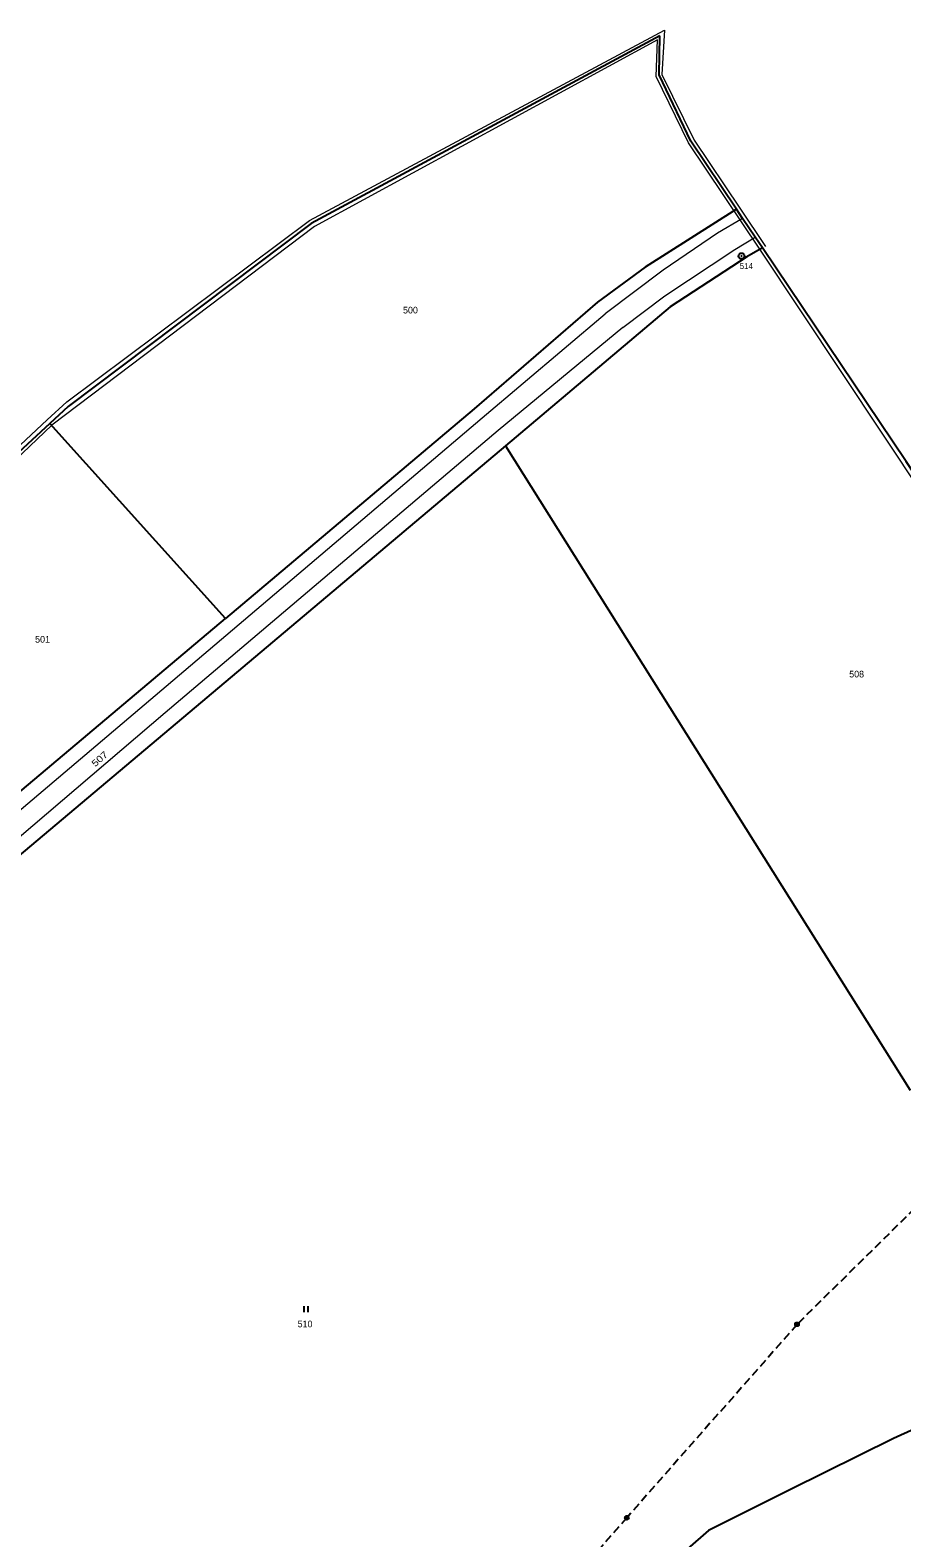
# Model space of a CAD drawing. Extents: x -653193 to -651624, y -1092017 to -1090260.
# Drawn here: x -652283.1 to -652060.5, y -1090861.4 to -1090476.4 of the extents above; entities that cross this region are included whole.
import ezdxf
from ezdxf.enums import TextEntityAlignment as Align

# ---------------------------------------------------------------- set-up
doc = ezdxf.new("R2010")
doc.units = 0
doc.header["$LTSCALE"] = 0.68
doc.linetypes.add('MEDIUM_DASHED', pattern=[4.5, 3, -1.5])
for name, color, linetype, lineweight in [('1', 7, 'Continuous', 25), ('3', 7, 'Continuous', 25), ('4', 7, 'Continuous', 13), ('6', 7, 'Continuous', 25), ('8', 7, 'Continuous', 25)]:
    doc.layers.add(name, color=color, linetype=linetype, lineweight=lineweight)
doc.layers.add('2', color=7, linetype='Continuous')

msp = doc.modelspace()

# ---------------------------------------------------------------- linework, layer by layer
at = {"layer": '1'}
for p, q in [((-652122.25, -1090477.85), (-652211.34, -1090525.8)), ((-652122.44, -1090487.8), (-652122.25, -1090477.85)), ((-652114.39, -1090504.78), (-652122.44, -1090487.8)), ((-652102.72, -1090522.13), (-652114.39, -1090504.78)), ((-652102.72, -1090522.13), (-652126.01, -1090536.93)), ((-652101.13, -1090524.49), (-652102.72, -1090522.13)), ((-652211.34, -1090525.8), (-652273.4, -1090572.52)), ((-652097.89, -1090529.3), (-652101.13, -1090524.49)), ((-652096.08, -1090531.99), (-652097.89, -1090529.3)), ((-652100.06, -1090534.33), (-652119.6, -1090547.06)), ((-652096.08, -1090531.99), (-652100.06, -1090534.33)), ((-652126.01, -1090536.93), (-652138.2, -1090545.89)), ((-652138.2, -1090545.89), (-652169.67, -1090573.11)), ((-652119.6, -1090547.06), (-652161.73, -1090582.58)), ((-652273.4, -1090572.52), (-652278.07, -1090576.84)), ((-652169.67, -1090573.11), (-652233.17, -1090626.65)), ((-652278.07, -1090576.84), (-652308.16, -1090604.7)), ((-652233.17, -1090626.65), (-652278.07, -1090576.84)), ((-652161.73, -1090582.58), (-652237.99, -1090646.81)), ((-652161.73, -1090582.58), (-652058.33, -1090747.05)), ((-652286.71, -1090671.78), (-652233.17, -1090626.65)), ((-652237.99, -1090646.81), (-652287.6, -1090688.58)), ((-652047.04, -1090828.95), (-652062.61, -1090836.05)), ((-652062.61, -1090836.05), (-652088.94, -1090849.09)), ((-652088.94, -1090849.09), (-652109.84, -1090859.51)), ((-652109.84, -1090859.51), (-652115.21, -1090864.22))]:
    msp.add_line(p, q, dxfattribs=at)
msp.add_lwpolyline([(-652012.34, -1090657.94), (-652059.39, -1090586.59), (-652096.08, -1090531.99)], dxfattribs=at)
at = {"layer": '3'}
for p, q in [((-652213.111, -1090803.78), (-652213.111, -1090802.28)), ((-652212.11, -1090803.78), (-652212.11, -1090802.28))]:
    msp.add_line(p, q, dxfattribs=at)
at = {"layer": '4'}
for p, q in [((-652101.13, -1090524.49), (-652107.52, -1090528.27)), ((-652107.52, -1090528.27), (-652121.4, -1090537.73)), ((-652103.13, -1090532.43), (-652097.89, -1090529.3)), ((-652120.97, -1090544.31), (-652103.13, -1090532.43)), ((-652121.4, -1090537.73), (-652136.24, -1090548.9)), ((-652131.72, -1090552.32), (-652120.97, -1090544.31)), ((-652167.64, -1090575.43), (-652136.24, -1090548.9)), ((-652131.72, -1090552.32), (-652163.57, -1090578.68)), ((-652251.17, -1090646.33), (-652167.64, -1090575.43)), ((-652163.57, -1090578.68), (-652248.6, -1090650.75)), ((-652289.3, -1090678.68), (-652251.17, -1090646.33)), ((-652248.6, -1090650.75), (-652289.95, -1090686.08))]:
    msp.add_line(p, q, dxfattribs=at)
for points in [[(-652394.94, -1090666.29), (-652333.98, -1090622.23), (-652308.65, -1090603.85), (-652278.77, -1090575.95), (-652273.68, -1090571.31), (-652211.73, -1090525.03), (-652121.11, -1090476.43), (-652121.78, -1090487.72), (-652113.48, -1090504.55), (-652101.85, -1090521.87), (-652095.29, -1090531.68)], [(-651924.64, -1090810.59), (-651944.72, -1090786.79), (-651953.83, -1090771.34), (-651957.54, -1090759.26), (-651970.54, -1090744.66), (-651971.3, -1090737.57), (-651990.03, -1090683.62), (-652010.36, -1090668.34), (-652012.98, -1090658.29), (-652096.76, -1090532.33), (-652114.98, -1090505.23), (-652123.25, -1090488.26), (-652122.91, -1090478.89), (-652210.49, -1090526.59), (-652277.57, -1090577.33), (-652307.52, -1090605.78), (-652393.41, -1090667.24), (-652434.16, -1090726.25)]]:
    msp.add_lwpolyline(points, dxfattribs=at)
at = {"layer": '6', "linetype": 'MEDIUM_DASHED'}
for p, q in [((-652037.57, -1090757.97), (-652087.24, -1090806.89)), ((-652087.24, -1090806.89), (-652130.7, -1090856.28)), ((-652130.7, -1090856.28), (-652183.19, -1090915.5))]:
    msp.add_line(p, q, dxfattribs=at)
at = {"layer": '6'}
for centre, radius in [((-652087.2434, -1090806.8899), 0.5), ((-652087.2434, -1090806.8899), 0.4), ((-652087.2434, -1090806.8899), 0.3), ((-652087.2434, -1090806.8899), 0.2), ((-652087.2434, -1090806.8899), 0.1), ((-652130.7034, -1090856.2799), 0.5), ((-652130.7034, -1090856.2799), 0.4), ((-652130.7034, -1090856.2799), 0.3), ((-652130.7034, -1090856.2799), 0.2), ((-652130.7034, -1090856.2799), 0.1)]:
    msp.add_circle(centre, radius, dxfattribs=at)
at = {"layer": '8'}
for radius in [0.75, 0.03]:
    msp.add_circle((-652101.44, -1090534.0998), radius, dxfattribs=at)

# ---------------------------------------------------------------- texts
at = {"layer": '2'}
for s, p in [('500', (-652185.959, -1090548.765)), ('501', (-652279.919, -1090632.825)), ('508', (-652072.019, -1090641.705)), ('510', (-652212.879, -1090807.625))]:
    msp.add_text(s, height=1.7, dxfattribs=at).set_placement(p, align=Align.CENTER)
at = {"layer": '2', "width": 1.2}
msp.add_text('507', height=1.7, rotation=41, dxfattribs=at).set_placement((-652264.7671, -1090663.1638), align=Align.CENTER)
at = {"layer": '8'}
msp.add_text('514', height=1.5, dxfattribs=at).set_placement((-652098.519, -1090537.424), align=Align.RIGHT)

doc.saveas('drawing.dxf')
